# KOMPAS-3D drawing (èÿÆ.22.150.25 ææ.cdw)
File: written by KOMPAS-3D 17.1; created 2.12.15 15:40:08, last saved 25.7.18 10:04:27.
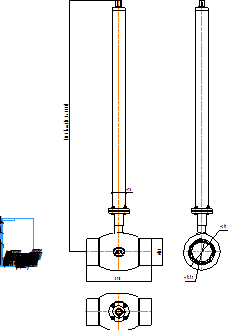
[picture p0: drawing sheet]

Sheet 1: A4, portrait

Title block, sheet 1: name: КШТ.22.150.25 С/С; sheets: 1; organisation: ООО "АДЛ Групп"; sheet format: A4; stored path: C:\Users\kka\KOMPAS_Work\Модели кранов для исследований\DN50\С удлинением\КШГ.32.050.40 СС ГЧ _ Шаровой кран БИВАЛ Ду50 Ру4 МПа редуцированный под приварку, с удлинением штока H=1100.cdw

Views: Вид 1, Спереди
Referenced files in C:\Users\kka\KOMPAS_Work\Модели кранов для исследований\DN150\С удлинением\: КШТ.22.150.25 СС.a3d, КШГ.35.125.25 СС Lстр600.a3d, КШГ.35.125.25 СС Lстр600.a3d!Деталь (локальная).m3d
Referenced files in C:\Users\kka\KOMPAS_Work\Модели кранов для исследований\DN150\: АПТА.0203-1938.04.01 _ Корпус крана  Ду150 (труба по ГОСТ).m3d, Шар150.m3d, АПТА.0203-2625.14.02 _ Пластина штока Ду150.m3d, корпштока150.m3d, АПТА.0203-2625.11.03 _ Подкладка для кольца Ду150-200.m3d, АПТА.0203-2625.14.01 _ Шток Ду150.m3d, АПТА.0203-2625.12.02 _ Шайба фрикционная Ду150-200.m3d, Втулка ГОСТ ИСО 3547-1-2006 30 В 34х30-Р1-С.m3d, АПТА.0203-2625.11.02 _ Крышка штока Ду150-200.m3d, Кольцо Viton 29.2x3.m3d, Кольцо EPDM 29.2x3.m3d, Фланецприв150.m3d, Шпонка 8х7х32 ГОСТ 23360-80.m3d, АПТА.0203-1938.00.00 _ Кран шаровой сварной Ду150 (Труба по ГОСТ).a3d!АПТА.0203-1938.00.00!Деталь (локальная).m3d, АПТА.0203-2625.02.03 _ Пружина тарельчатая Ду150.m3d, АПТА.0203-2625.02.02 _ Кольцо горловое Ду150.m3d, АПТА.0203-2625.02.05 _ Уплотнение седловое Ду150.m3d, АПТА.0203-2625.02.04 _ Кольцо опорное Ду150.m3d, АПТА.0203-1938.03.01 _ Патрубок сварной точенный Ду150 (труба по ГОСТ).m3d, АПТА.0203-1938.00.00 _ Кран шаровой сварной Ду150 (Труба по ГОСТ).a3d!АПТА.0203-1938.00.00!Деталь (локальная) 1.m3d, АПТА.0203-1938.00.00 _ Кран шаровой сварной Ду150 (Труба по ГОСТ).a3d!АПТА.0203-1938.00.00!Деталь (локальная) 1 1.m3d, АПТА.0203-1938.00.00 _ Кран шаровой сварной Ду150 (Труба по ГОСТ).a3d!АПТА.0203-1938.00.00!Деталь (локальная) 2.m3d, АПТА.0203-2625.03.03 _ Втулка Ду150.m3d, АПТА.0203-2625.03.01 _ Рукоятка Ду150.m3d, АПТА.0203-2625.03.00 _ Ручка Ду150.a3d, АПТА.0203-1938.00.00 _ Кран шаровой сварной Ду150 (Труба по ГОСТ).a3d
Referenced files in C:\Program Files\ASCON\KOMPAS-3D v17\Libs\PartLib\DATA\VAULT\methods\kompas\3d\: PLib_Check_spring_rings_GOST_13942_911.m3d, PLib_Pins_GOST_10733_911.m3d, PLib_Screw_GOST_8878-84_900.m3d, PLib_Bolt_1_900.m3d, PLib_Washer_1_712.m3d, PLib_Washer_2_712.m3d, PLib_Nut_OST92_900.m3d
Referenced files in C:\Users\kka\KOMPAS_Work\!Trash\Редукторы\Редуктор серии Q\компас 3d\: Q-800-S.m3d
Referenced files in C:\Users\kka\KOMPAS_Work\!Trash\Штурвалы\: Штурвал W250_15.m3d
Referenced files in C:\Users\kka\KOMPAS_Work\Модели кранов для исследований\DN200\: АПТА.0203-2625.03.02 _ Пластина стопорная Ду150.m3d
Referenced files in C:\Users\kka\KOMPAS_Work\Модели кранов для исследований\DN65\: АПТА.0203-2617.03.03 _ Ухватка Ду65-200.m3d
Referenced files in C:\Users\kka\KOMPAS_Work\Удлинения БИВАЛ ф. ADL\Небюджет\Удлинения_2010\УШДн150\: УШ.286.00.02 _ Фланец Ду150.m3d, УШ.286.01.01 _ Втулка верхняя Ду150.m3d, УШ.286.01.01-01 _ Втулка нижняя Ду150.m3d, УШ.286.00.01 _ Прокладка Ду150.m3d, УШ.286.00.00 _ Удлинение штока Ду150.a3d!УШ.286.00.00!Деталь (локальная).m3d, УШ.286.00.00 _ Удлинение штока Ду150.a3d!УШ.286.00.00!Деталь (локальная) 1.m3d, УШ.286.01.04 _ Штифт Ду150.m3d, УШ.286.00.00 _ Удлинение штока Ду150.a3d
Referenced files in C:\Users\kka\KOMPAS_Work\Удлинения БИВАЛ ф. ADL\Небюджет\Удлинения_2010\УШДн40-50\: УШ.261.00.06 _ Кольцо запорное Ду20-150.m3d
Referenced files in C:\Users\kka\KOMPAS_Work\Удлинения БИВАЛ ф. ADL\Небюджет\Удлинения_2010\УШДн100\: Шток_100.m3d, УШ.276.00.06 _ Крышка корпуса Ду100-150.m3d, Шпонка 8х7х40 ГОСТ 23360-80.m3d
Referenced files in C:\Users\kka\KOMPAS_Work\!Trash\АГТО 099.00.00 Кран для выставки Ду150 ПП П-Э патрубки\Удлинение 200\: Кольцо 036-041-30-1-2 ГОСТ 9833-73ГОСТ 18829-73.m3d
Referenced files in C:\Users\kka\KOMPAS_Work\Модели кранов для исследований\DN150\С удлинением\КШТ.22.150.25 СС.a3d!КШТ.22.150.25 С\: С!Деталь (локальная).m3d
Referenced files in C:\Users\kka\KOMPAS_Work\Модели кранов для исследований\DN80\С удлинением\: КШТ.22.080.25 СС.a3d
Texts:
  Klimkovich
  ADL
  (от 410 до 5000)
  Рама для чертежей
  Лит-Масса-Масштаб
  Материал-Предприятие
  Масштаб
  Изм.
  Лист
  № докум.
  Подп.
  Дата
  Лит.
  Разраб.
  Пров.
  Т.контр.
  Листов
  Внимание! Данный продукт является объектом авторского права ООО «Торговый Дом АДЛ».
  Запрещается изменение, копирование, распространение
  (в том числе путем копирования на другие сайты и ресурсы в Интернете)
  или любое иное использование информации и объектов без предварительного
  согласия правообладателя (ООО «Торговый Дом АДЛ»).
  Н.контр.
  Утв.
  ООО "Торговый дом АДЛ"
  Изменение
  Номер документа
  Подпись
  Обозначение документа
  Наименование изделия
  Масса изделия по ГОСТ 2.109-73
  Порядковый номер листа
  Общее количество листов в документе
  Характер работы, выполненной лицом, подписавшим документ
  Наименование или индекс предприятия, выпускающего документ
  Инв. № подл.
  Подп. и дата
  Взам. инв. №
  Инв. № дубл.
  Инвентарный номер подлинника по ГОСТ 2.501-68
  Подпись принявшего подлинник в отдел технической документации
  Инвентарный номер подлинника, взамен которого выпущен данный подлинник
  Инвентарный номер дубликата по ГОСТ 2.502-68
  Подпись принявшего дубликат в отдел технической документации
  Справ. №
  Перв. примен.
  Обозначение документа, взамен или на основании которого выпущен данный документ
  Обозначение документа, в котором впервые записан данный документ
  Подпись лица, копировавшего чертеж
  Обозначение формата листа
  !Рама для чертежа
  Корпус крана  Ду150 (труба по ГОСТ)
  АПТА.0203-1938.04.01
  Шар Ду150
  АПТА.0203-2625.11.01
  Пластина штока Ду150
  АПТА.0203-2625.14.02
  Корпус штока Ду150
  Подкладка для кольца Ду150-200
  АПТА.0203-2625.11.03
  Шток Ду150
  АПТА.0203-2625.14.01
  Шайба фрикционная Ду150-200
  АПТА.0203-2625.12.02
  Втулка ГОСТ ИСО 3547-1-2006 30 В 34х30-Р1-С
  Крышка штока Ду150-200
  АПТА.0203-2625.11.02
  Кольцо Viton 29.2x3
  Кольцо EPDM 29.2x3
  Фланец приварной Ду150
  Шпонка 8х7х32 ГОСТ 23360-80
  Деталь (локальная)
  Кольцо A30.50 ХГА ГОСТ 13942-86
  Пружина тарельчатая Ду150
  АПТА.0203-2625.02.03
  Кольцо горловое Ду150
  АПТА.0203-2625.02.02
  Уплотнение седловое Ду150
  АПТА.0203-2625.02.05
  Кольцо опорное Ду150
  АПТА.0203-2625.02.04
  Патрубок сварной точенный Ду150 (труба по ГОСТ)
  АПТА.0203-1938.03.01
  Штифт 12x24 ГОСТ 10773-93
  Редуктор Q-800-S ф.ProGear
  Пластина стопорная Ду150
  АПТА.0203-2625.03.02
  Втулка Ду150
  АПТА.0203-2625.03.03
  Рукоятка Ду150
  АПТА.0203-2625.03.01
  Ухватка Ду65-200
  АПТА.0203-2617.03.03
  Ручка Ду150
  АПТА.0203-2625.03.00
  Винт М6-6gx10.14H.019 ГОСТ 8878-93
  Кран шаровой сварной Ду150 (Труба по ГОСТ)
  АПТА.0203-1938.00.00
  Фланец Ду150
  УШ.286.00.02
  УШ.286.01.01
  УШ.286.01.01-01
  Прокладка Ду150
  УШ.286.00.01
  Кольцо запорное Ду20-150
  УШ.261.00.06
  Удлинитель
  Корпус
  Кольцо A36.65 ГОСТ 13942-86
  Болт М10-6gx50.68.019 ГОСТ 7796-70
  Шайба A.10.04.019 ГОСТ 11371-78
  Шайба 10 65Г 019 ГОСТ 6402-70
  Гайка М10-6H.04.019 ГОСТ 5927-70
  Головка штока Ду100-150
  УШ.276.00.02
  Крышка корпуса Ду100-150
  УШ.276.00.06
  Шпонка 8х7х40 ГОСТ 23360-80
  Кольцо 036-041-30-1-2 ГОСТ 9833-73/ГОСТ 18829-73
  Штифт Ду150
  УШ.286.01.04
  Удлинение штока Ду150
  УШ.286.00.00
Dimensions and other numbers on the sheet: 76; 1500; 390; 159; 1:1; 1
